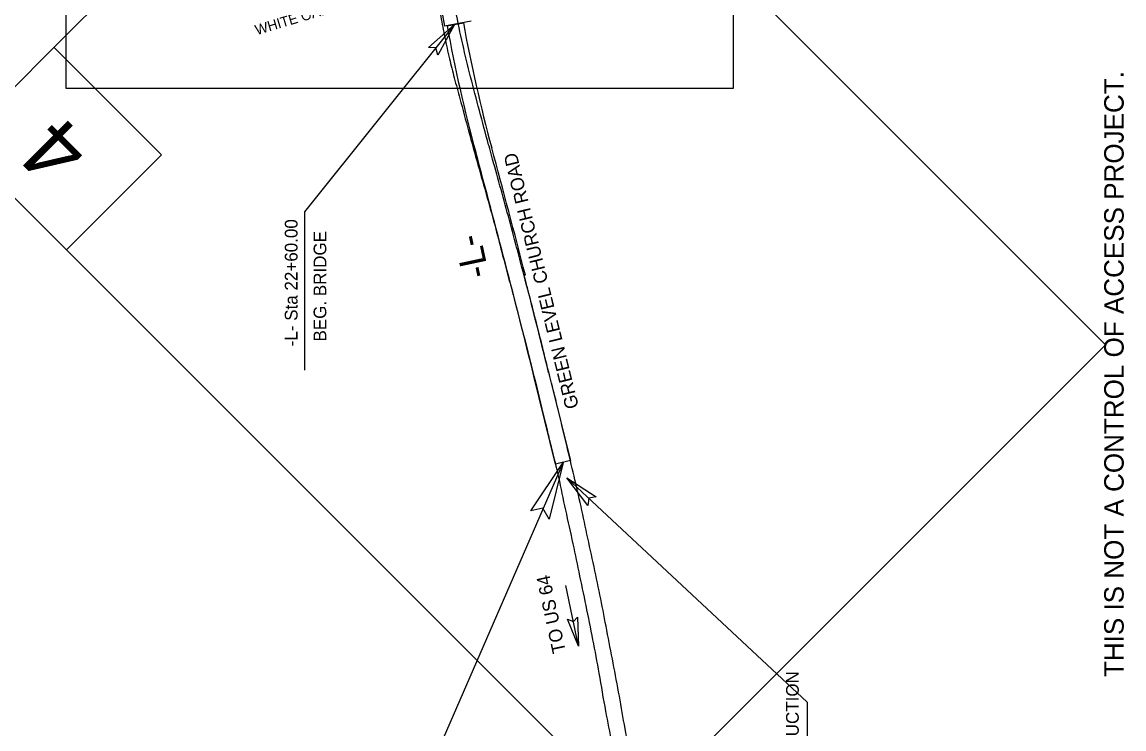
# Model space of a CAD drawing. Extents: x 2026893 to 2039781, y 729195 to 739590.
# Drawn here: x 2028226 to 2029959, y 736122 to 737234 of the extents above; entities that cross this region are included whole.
import ezdxf

# ---------------------------------------------------------------- set-up
doc = ezdxf.new("R2010")
doc.units = 0
for name, color, linetype in [('Default', 7, 'Continuous'), ('Old_Level_1', 7, 'Continuous'), ('Old_Level_11', 7, 'Continuous'), ('Old_Level_2', 7, 'Continuous'), ('Old_Level_20', 7, 'Continuous'), ('Old_Level_22', 7, 'Continuous'), ('Old_Level_3', 7, 'Continuous'), ('Prop Shade Heavy', 7, 'Continuous'), ('Prop Shade Light', 7, 'Continuous'), ('Prop Terminator CELL', 7, 'Continuous')]:
    doc.layers.add(name, color=color, linetype=linetype)

msp = doc.modelspace()

# ---------------------------------------------------------------- linework, layer by layer
at = {"layer": 'Old_Level_1'}
for p, q in [((2028905.8, 737230.1), (2028669.9, 736935.2)), ((2028669.9, 736935.2), (2028669.9, 736686.1)), ((2029076.3, 736541), (2028856.5, 736034.7)), ((2029460.3, 736163.9), (2029082.2, 736516.7)), ((2029460.3, 736163.9), (2029460.3, 735893.8))]:
    msp.add_line(p, q, dxfattribs=at)
at = {"layer": 'Old_Level_2'}
msp.add_line((2029100.9, 736251.8), (2029080.5, 736347.2), dxfattribs=at)
at = {"layer": 'Old_Level_20'}
msp.add_line((2028868.8, 737786.8), (2028294.4, 737212.4), dxfattribs=at)
at = {"layer": 'Old_Level_22'}
for p, q in [((2028294.4, 738629.8), (2028294.4, 737129.7)), ((2029344.4, 737129.7), (2029344.4, 738629.7)), ((2029929.5, 736726.1), (2029344.4, 737311.2)), ((2028894, 737228), (2028919.6, 737232.6)), ((2028294.4, 737212.4), (2028126.3, 737044.3)), ((2028445.1, 737024.7), (2028275.9, 737193.9)), ((2028294.4, 737129.7), (2029344.4, 737129.7)), ((2028126.3, 737044.3), (2029187.1, 735983.6)), ((2028295.5, 736875.1), (2028445.1, 737024.7)), ((2029017.1, 736835.6), (2029015.2, 736835.1)), ((2029187.1, 735983.6), (2029929.5, 736726.1)), ((2029064.7, 736538.2), (2029030.4, 736676.8)), ((2029053.7, 736682.5), (2029088, 736543.9)), ((2029088, 736543.9), (2029064.7, 736538.2))]:
    msp.add_line(p, q, dxfattribs=at)
for centre, radius, start, end in [((2031266.9, 737660.6), 2412, 190.3323, 195.1822), ((2031266.9, 737660.6), 2386, 190.3323, 195.1822), ((2013389.9, 732809.6), 16137.5, 14.44682, 15.18187), ((2013389.9, 732809.8), 16111.5, 13.88754, 15.18122), ((2013389.8, 732810), 16135.5, 13.88669, 14.44532)]:
    msp.add_arc(centre, radius, start, end, dxfattribs=at)
at = {"layer": 'Old_Level_3'}
for p, q in [((2028960.1, 737038.2), (2028959.3, 737040.6)), ((2028961, 737034.8), (2028960.1, 737038.2)), ((2029055.6, 736676.2), (2029054.9, 736678.8)), ((2029058.3, 736665.5), (2029056.1, 736674))]:
    msp.add_line(p, q, dxfattribs=at)
for points in [[(2029030.8, 736675.2), (2029032.8, 736667.9)], [(2029056.1, 736674), (2029055.6, 736676.2)], [(2029032.8, 736667.9), (2029044.8, 736618.5), (2029051.3, 736592)]]:
    msp.add_lwpolyline(points, dxfattribs=at)
for points in [[(2028876, 737297.4), (2028877.7, 737280.7), (2028884.1, 737242.4), (2028890.4, 737209.5), (2028897.8, 737176.1), (2028905.3, 737145.9), (2028914.1, 737113.4), (2028927.8, 737062.5), (2028942.5, 737009), (2028956.7, 736958.8), (2028970.6, 736908.1), (2028981.4, 736866.4), (2028994.6, 736816.4), (2029007.2, 736768.1), (2029020.4, 736717.4), (2029030.8, 736675.2)], [(2028959.3, 737040.6), (2028944.8, 737094.7), (2028931, 737147.5), (2028918.6, 737198.8), (2028907.8, 737251.5), (2028901.5, 737300.9)], [(2029054.9, 736678.8), (2029043.8, 736723.1), (2029031.6, 736772.7), (2029018.6, 736821.4), (2029005, 736873.6), (2028992, 736922.2), (2028978.8, 736970.3), (2028965.6, 737018.1), (2028961, 737034.8)], [(2029188.1, 736024.5), (2029181.9, 736072.6), (2029173.9, 736121.9), (2029164.9, 736173.1), (2029155.2, 736225.3), (2029145.2, 736276.8), (2029135.6, 736326.4), (2029125.1, 736376.8), (2029113.9, 736428), (2029103.3, 736477.9), (2029092.2, 736525.4), (2029080.7, 736574), (2029068.6, 736624.3), (2029058.3, 736665.5)], [(2029051.3, 736592), (2029056.9, 736568.1), (2029067.7, 736524), (2029078.7, 736472.6), (2029090.4, 736419.4), (2029101.1, 736368.5), (2029112.1, 736315.7), (2029122.9, 736262), (2029132.8, 736209.1), (2029143.2, 736149.3), (2029152.8, 736099), (2029158.3, 736062.4), (2029163.1, 736020)]]:
    msp.add_spline(points, degree=3, dxfattribs=at)
at = {"layer": 'Prop Shade Heavy'}
msp.add_line((2028931.9, 737234.9), (2028890.1, 737227.3), dxfattribs=at)
msp.add_arc((2031266.9, 737660.6), 2416, 183.6478, 190.3323, dxfattribs=at)
at = {"layer": 'Prop Shade Light'}
for p, q in [((2028894, 737228), (2028919.6, 737232.6)), ((2029017.1, 736835.6), (2029015.2, 736835.1)), ((2029064.7, 736538.2), (2029030.4, 736676.8)), ((2029053.7, 736682.5), (2029088, 736543.9)), ((2029088, 736543.9), (2029064.7, 736538.2))]:
    msp.add_line(p, q, dxfattribs=at)
for centre, radius, start, end in [((2031266.9, 737660.6), 2412, 190.3323, 195.1822), ((2031266.9, 737660.6), 2386, 190.3323, 195.1822), ((2013389.9, 732809.6), 16137.5, 14.44682, 15.18187), ((2013389.9, 732809.8), 16111.5, 13.88754, 15.18122), ((2013389.8, 732810), 16135.5, 13.88669, 14.44532)]:
    msp.add_arc(centre, radius, start, end, dxfattribs=at)
at = {"layer": 'Prop Terminator CELL'}
for points in [[(2028864.8, 737193.8), (2028905.8, 737230.1), (2028879.4, 737181.7), (2028876.2, 737193.1)], [(2029025.9, 736464.9), (2029076.3, 736541), (2029054.6, 736451.7), (2029044.6, 736468.7)], [(2029115.3, 736473.1), (2029082.2, 736516.7), (2029128.4, 736486.7), (2029116.8, 736484.4)], [(2029099.1, 736297.5), (2029100.9, 736251.8), (2029083.6, 736294.4), (2029092.6, 736290.5)]]:
    msp.add_lwpolyline(points, close=True, dxfattribs=at)

# ---------------------------------------------------------------- texts
at = {"layer": 'Default'}
msp.add_text('THIS IS NOT A CONTROL OF ACCESS PROJECT.', height=30.625, rotation=90, dxfattribs=at).set_placement((2029958.1, 736203.2))
at = {"layer": 'Old_Level_1'}
for s, height, rotation, p in [('-L- Sta 22+60.00', 20, 90, (2028658.8, 736723.6)), ('BEG. BRIDGE', 20, 90, (2028704.1, 736731.1)), ('-L-', 42, 102.0876, (2028960.3, 736835.3)), ('BEGIN CONSTRUCTION', 20, 90, (2029447.1, 735906.4))]:
    msp.add_text(s, height=height, rotation=rotation, dxfattribs=at).set_placement(p)
at = {"layer": 'Old_Level_11'}
msp.add_text('WHITE OAK CREEK', height=16, rotation=16.6525, dxfattribs=at).set_placement((2028594.8, 737213.1))
at = {"layer": 'Old_Level_2'}
for s, rotation, p in [('GREEN LEVEL CHURCH ROAD', 103.7617, (2029101.4, 736628)), ('TO US 64', 102.0876, (2029080.9, 736243.1))]:
    msp.add_text(s, height=21, rotation=rotation, dxfattribs=at).set_placement(p)
at = {"layer": 'Old_Level_22'}
msp.add_text('4', height=100, rotation=135, dxfattribs=at).set_placement((2028338.3, 737038))

doc.saveas('drawing.dxf')
